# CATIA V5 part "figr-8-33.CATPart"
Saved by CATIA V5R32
Part number: Part1
Bounding box of the stored display mesh (mm): x -75 to 75, y -75 to 75, z 0 to 20
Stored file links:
  D:\PROJECTS\Project 2022\CATIA V5 6R 2022\Resources\Part Files\c08_catia_v5_6r2022_prt\figr-8-33.CATPart
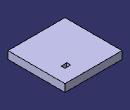
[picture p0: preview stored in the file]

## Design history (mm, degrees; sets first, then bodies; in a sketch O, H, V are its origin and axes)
Body1 (main body)
  Sketch1 on xy-plane, origin (0, 0, 0), H (1, 0, 0), V (0, 1, 0)
    line L1 (-75, 75) -> (75, 75)
    line L2 (75, 75) -> (75, -75)
    line L3 (75, -75) -> (-75, -75)
    line L4 (-75, -75) -> (-75, 75)
    axis line L5 (75, -75) -> (-75, 75)
    length L3 = 150
    length L2 = 150
    horizontal: L1 H, L3 H
    vertical: L2 V, L4 V
    midpoint: O L5
  Pad1: profile Sketch1, direction (0, 0, 1), length 20
  Sketch2 on face of Pad1, origin (0, 0, 20), H (1, 0, 0), V (0, 1, 0)
    line L1 (25, 40) -> (40, 40)
    line L2 (40, 40) -> (40, 30)
    line L3 (40, 30) -> (25, 30)
    line L4 (25, 30) -> (25, 40)
    reference projected line E1 (75, -75) -> (75, 75) from edge [face of Pad1 | face of Pad1]
    reference projected line E2 (75, 75) -> (-75, 75) from edge [face of Pad1 | face of Pad1]
    length L3 = 15
    length L4 = 10
    distance L2 E1 = 35
    distance L1 E2 = 35
    horizontal: L1 H, L3 H
    vertical: L2 V, L4 V
  Pocket1: profile Sketch2, direction (0, 0, -1), through (limit type 3)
